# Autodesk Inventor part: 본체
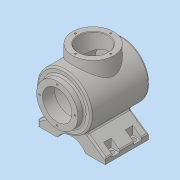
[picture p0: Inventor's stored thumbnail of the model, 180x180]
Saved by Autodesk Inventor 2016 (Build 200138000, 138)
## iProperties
Created: 2021-04
Part Number: 본체
Material: Generic
Document SubType Name: Modeling
Designer: User
Density: 1 g/cm^3
Appearance: Default
Author: User
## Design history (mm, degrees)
sketch "스케치1"
  geometry: C1 r 50 at (0, 0)
  constraints: 1 centre point
  dimensions: "d2" = 100 diameter of C1
extrude "돌출1" new body sketch "스케치1" distance "d3" = 108; taper "d4" = 0 deg
node "작업 평면1"
sketch "스케치3"
  geometry: L1 (-62, -77)-(62, -77); L2 (-62, -77)-(-62, -67); L3 (-62, -67)-(-26.694, -42.278); L4 (62, -77)-(62, -67); L5 (62, -67)-(26.694, -42.278); L6 (-26.694, -42.278)-(26.694, -42.278); A1 r 50 centre (0, 0) between (26.694, -42.278) and (-26.694, -42.278) reference; 2 further points
  constraints: 12 end point, 2 point on circle, 2 vertical, 1 horizontal, 1 midpoint, 1 vertical alignment
  dimensions: "d5" = 124 distance of L1.start L1.end; "d8" = 77 distance from line of L1 point (0, 0); "d60" = 55 deg angle of L3 L2; "d61" = 10 distance of L1.start L2.end; "d62" = 55 deg angle of L5 L4; "d63" = 10 distance of L1.end L4.end
extrude "돌출2" join sketch "스케치3" stored distance "d9" = 80; taper "d10" = 0 deg
sketch "스케치4" dims "d12" = 30
  geometry: L1 (-62, -77)-(62, -77) reference; 4 further points
  constraints: 2 vertical alignment, 1 midpoint, 2 other
  dimensions: "d13" = 15 distance from line of L1 point (0, -62)
extrude "돌출3" cut sketch "스케치4" distance "d14" = 80; taper "d15" = 0 deg
node "작업 평면2"
sketch "스케치5"
  geometry: L1 (12, -14)-(112, -14) reference; L2 (12, 94)-(112, 94) reference; L3 (112, 94)-(112, -14) reference; L4 (12, 94)-(12, -14) reference; C1 r 38 at (62, 40); 3 further points
  constraints: 2 midpoint, 1 centre point, 1 horizontal alignment, 1 vertical alignment
  dimensions: "d17" = 76 diameter of C1
extrude "돌출4" join sketch "스케치5" stored distance "d18" = 80; taper "d19" = 0 deg
sketch "스케치9"
  geometry: 1 further point
sketch "스케치11"
  geometry: C1 r 27 at (0, 0); 1 further point
  constraints: 1 centre point
  dimensions: "d25" = 54 diameter of C1
extrude "돌출5" cut sketch "스케치11" distance "d26" = 47.5; taper "d27" = 0 deg
sketch "스케치12" dims "d28" = 65
  geometry: 3 further points
  constraints: 1 horizontal alignment, 2 other
hole "구멍1" sketch "스케치12" at (-32.5, 0) diameter "d29" = 3.242; stored, may be unused: countersink angle "d33" = 90 deg, drill point angle "d35" = 118 deg; dims "d30" = 8, "d31" = 4, "d32" = 2, "d34" = 11.8
node "작업 평면3"
sketch "스케치14"
  geometry: C1 r 38 at (0, 0); 1 further point
  constraints: 1 centre point, 1 coincident
  dimensions: "d41" = 76 diameter of C1
extrude "돌출6" join sketch "스케치14" stored distance "d42" = 47.5; taper "d43" = 0 deg
sketch "스케치15"
  geometry: L1 (-38, 12)-(38, 12) reference; L2 (-50, -108)-(50, -108) reference; L3 (0, 12)-(0, -108); L4 (27, 12)-(27, -10); L5 (27, -10)-(40, -10); L6 (40, -10)-(40, -98); L7 (40, -98)-(0, -98); L8 (27, 12)-(0, 12); 1 further point
  constraints: 12 end point, 3 perpendicular, 2 midpoint, 2 point on line, 1 collinear, 1 vertical
  dimensions: "d44" = 54 diameter of L4 L3; "d45" = 80 diameter of L6 L3; "d46" = 22 distance of L4.start L4.end; "d47" = 10 distance from line of L2 L6.end
revolve "회전2" sketch "스케치15" stored, may be unused: angle "d48" = 90 deg
sketch "스케치16" dims "d49" = 65
  geometry: 3 further points
  constraints: 1 coincident, 1 vertical alignment, 2 other
hole "구멍2" sketch "스케치16" at (0, 32.5) diameter "d50" = 3.242; stored, may be unused: countersink angle "d54" = 90 deg, drill point angle "d56" = 118 deg; dims "d51" = 8, "d52" = 4, "d53" = 2, "d55" = 10
sketch "스케치17"
  geometry: L1 (0, 80)-(36.019, 80) reference; L2 (0, 80)-(0, 0) reference; C1 r 4.5 at (8, 60); 2 further points
  constraints: 1 centre point, 1 coincident
  dimensions: "d64" = 8 distance from line of L2 point (8, 60); "d65" = 20 distance from line of L1 point (8, 60); "d66" = 9 diameter of C1
extrude "돌출7" cut sketch "스케치17" distance "d67" = 47.5; taper "d68" = 0 deg
node "작업 평면4"
sketch "스케치18"
  geometry: L1 (-8, 53)-(0, 53); L2 (0, 0)-(0, 80) reference; L3 (-8, 67)-(0, 67); L4 (0, 53)-(0, 67); C1 r 4.5 at (-8, 60) reference; A1 r 7 centre (-8, 60) between (-8, 67) and (-8, 53); 1 further point
  constraints: 6 end point, 2 horizontal, 2 point on circle, 2 point on line, 1 centre point, 1 coincident, 1 collinear, 1 tangent
  dimensions: "d70" = 14 diameter of A1
extrude "돌출8" cut sketch "스케치18" distance "d71" = 19; taper "d72" = 0 deg
fillet "모깎기1" dims "d79" = 3
chamfer "모따기1" distance "d80" = 1; stored, may be unused: second distance "d81" = 2, angle "d82" = 45 deg
fillet "모깎기2" dims "d83" = 3
fillet "모깎기4" dims "d85" = 3
fillet "모깎기5" dims "d86" = 3
node "작업 평면5"
sketch "스케치19"
  geometry: L1 (8, 67)-(16, 67) reference; L2 (16, 53)-(8, 53) reference; L3 (0, 0)-(0, 80) reference; L4 (8, 67)-(16, 67) reference; L5 (8, 67)-(0, 67); L6 (0, 0)-(0, 80) reference; L7 (16, 53)-(8, 53) reference; L8 (0, 53)-(8, 53); L9 (8, 53)-(8, 67); L10 (0, 67)-(0, 53); 1 further point
  constraints: 8 end point, 3 point on line, 2 collinear, 1 perpendicular
extrude "돌출9" cut sketch "스케치19" distance "d89" = 19; taper "d90" = 0 deg
fillet "모깎기7" dims "d94" = 3
fillet "모깎기8" dims "d101" = 3
sketch "스케치25"
  geometry: C1 r 50 at (0, 0) reference; A1 r 47 centre (0, 0) between (0, 47) and (47, 0) reference; 3 further points
  constraints: 2 horizontal alignment, 2 point on circle, 1 coincident, 1 vertical alignment, 2 other
feature "엠보싱1" sketch "스케치25" dims "d102" = 0.5, "d103" = 0
node "솔리드1"
pattern_circular "원형 패턴1" dims angle "d37" = 360 deg
pattern_circular "원형 패턴2" dims angle "d58" = 360 deg
pattern_linear "직사각형 패턴1" dims "d78" = 108
pattern_linear "직사각형 패턴2" dims "d93" = 40
other parameters: "d16" = -142, "d40" = 12, "d69" = -25, "d88" = -25
